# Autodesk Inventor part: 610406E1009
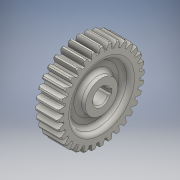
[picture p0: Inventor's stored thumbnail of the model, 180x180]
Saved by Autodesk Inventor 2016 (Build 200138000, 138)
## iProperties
Created: 2021-04
Part Number: 610406E1009
Material: 강철, 가공됨
Document SubType Name: Modeling
Designer: PC-1-3
Density: 7.85 g/cm^3
Appearance: 강철
Author: PC-1-3
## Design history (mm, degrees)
sketch "스케치1"
  geometry: L1 (-9, 0)-(9, 0); L2 (-9, 6)-(9, 6); L3 (9, 6)-(9, 12.5); L4 (9, 12.5)-(3, 12.5); L5 (3, 12.5)-(3, 22.5); L6 (3, 22.5)-(9, 22.5); L7 (9, 22.5)-(9, 29.5); L8 (9, 29.5)-(-9, 29.5); L9 (-9, 29.5)-(-9, 22.5); L10 (-9, 22.5)-(-3, 22.5); L11 (-3, 22.5)-(-3, 12.5); L12 (-3, 12.5)-(-9, 12.5); L13 (-9, 6)-(-9, 12.5); 2 further points
  constraints: 26 end point, 8 perpendicular, 7 point on line, 2 horizontal, 2 vertical alignment, 1 coincident, 1 midpoint
  dimensions: "d0" = 18 distance of L1.start L1.end; "d1" = 12 diameter of L2 L1; "d2" = 25 diameter of L12 L1; "d3" = 45 diameter of L10 L1; "d4" = 59 diameter of L8 L1; "d5" = 6 distance between parallel lines of L5 L11; "d6" = 6 distance between parallel lines of L11 L9
revolve "회전1" sketch "스케치1" stored, may be unused: angle "d7" = 90 deg
sketch "스케치3"
  geometry: L1 (-2, 5.657)-(-2, 7.8); L2 (-2, 7.8)-(2, 7.8); L3 (2, 7.8)-(2, 5.657); A1 r 6 centre (0, 0) between (-2, 5.657) and (2, 5.657) reference; 1 further point
  constraints: 6 end point, 2 perpendicular, 2 point on circle, 1 parallel, 1 vertical
  dimensions: "d8" = 13.8 dimension on A1 L2; "d9" = 4 distance of L1.end L2.end
extrude "돌출1" cut sketch "스케치3" stored distance "d10" = 10; taper "d11" = 0 deg
sketch "스케치4"
  geometry: L1 (0, 0)-(0, 34); L2 (-0.57, 29.494)-(-0.57, 33.995); L3 (-1.57, 29.458)-(-1.57, 33.964); L4 (-2.07, 29.427)-(-2.07, 33.937); C1 r 32 at (0, 0); C2 r 22.5 at (0, 0) reference; A1 r 34 centre (0, 0) between (0, 34) and (-0.57, 33.995); A2 r 29.5 centre (0, 0) between (-0.57, 29.494) and (-1.57, 29.458) reference; A3 r 9.275 centre (7.191, 28.917) between (-0.57, 33.995) and (-2.07, 29.427); A4 r 9.275 centre (-7.191, 28.917) between (2.07, 29.427) and (0.57, 33.995); A5 r 29.5 centre (0, 0) between (2.07, 29.427) and (-2.07, 29.427); A6 r 34 centre (0, 0) between (0.57, 33.995) and (-0.57, 33.995); 1 further point
  constraints: 15 point on circle, 8 end point, 6 centre point, 4 coincident, 4 vertical, 3 symmetric about line, 1 other
  dimensions: "d12" = 64 diameter of C1; "d13" = 68 diameter of A1; "d14" = 1.57 distance between parallel lines of L3 L1; "d15" = 1 distance between parallel lines of L2 L3; "d16" = 0.5 distance between parallel lines of L3 L4
extrude "돌출2" join sketch "스케치4" stored distance "d17" = 10; taper "d18" = 0 deg
chamfer "모따기1" distance "d19" = 1; stored, may be unused: second distance "d20" = 2, angle "d21" = 45 deg
fillet "모깎기1" dims "d25" = 3
chamfer "모따기2" distance "d26" = 1; stored, may be unused: second distance "d27" = 2, angle "d28" = 45 deg
node "솔리드1"
pattern_circular "원형 패턴1" dims angle "d23" = 360 deg
node "투영된 루프1"
